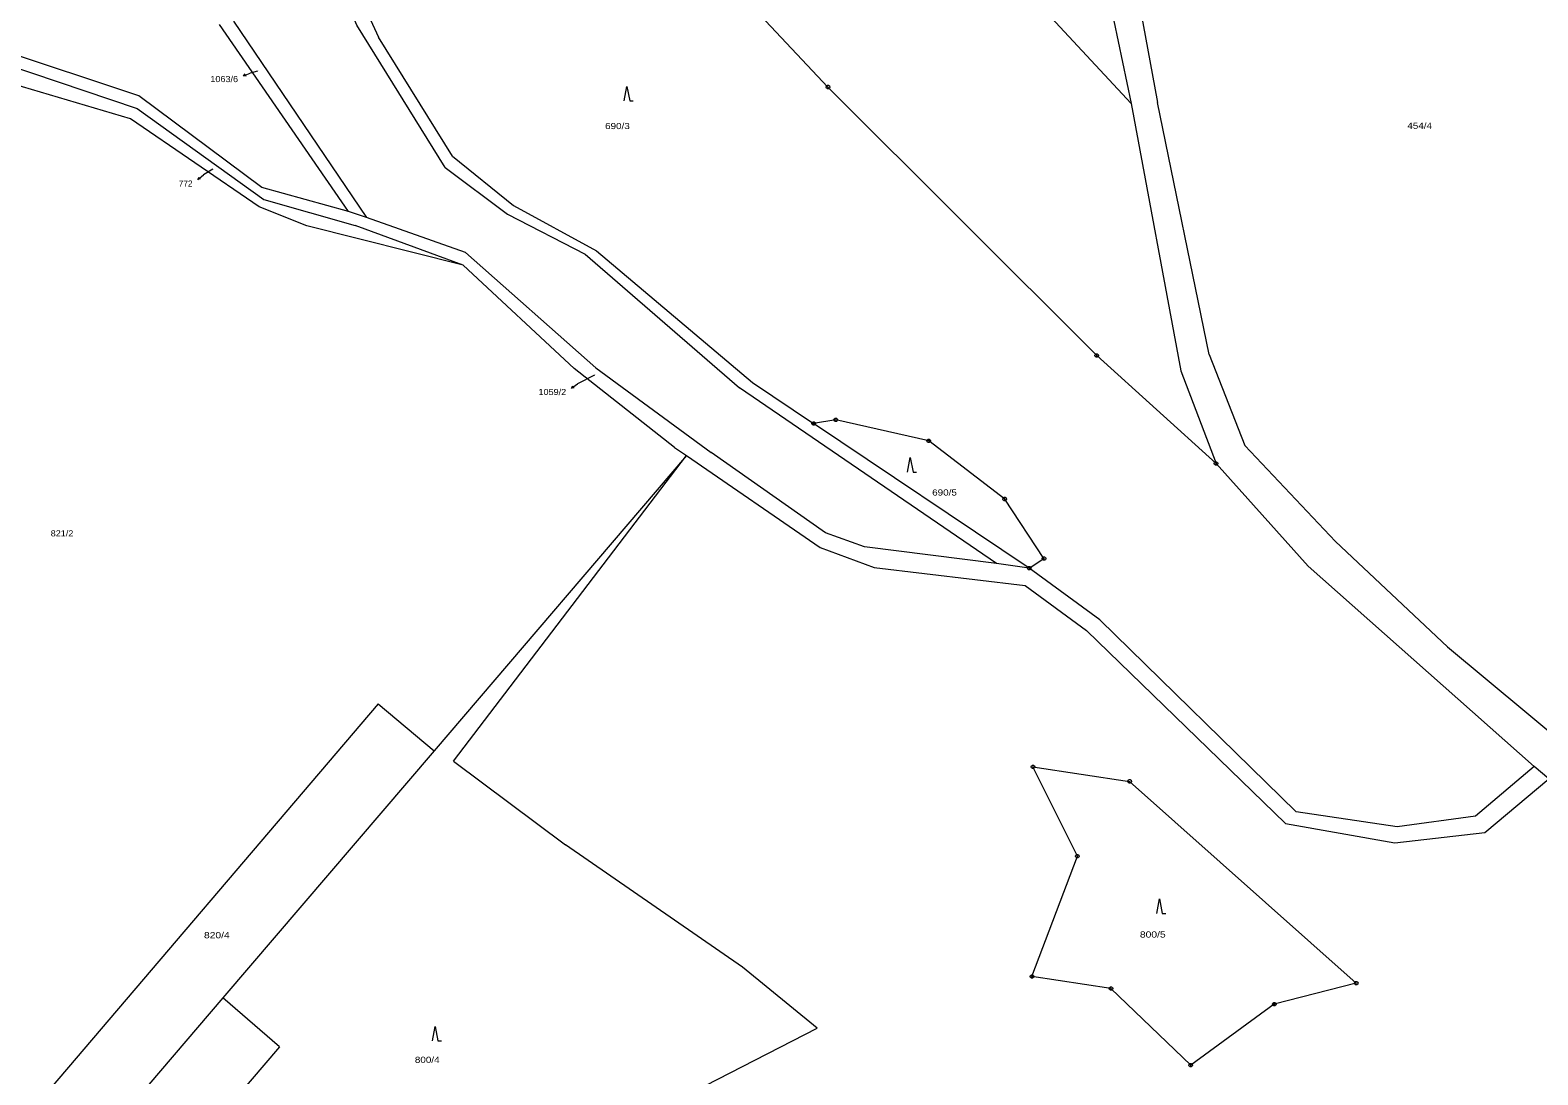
# Model space of a CAD drawing. Extents: x -687390 to -684106, y -954833 to -951648.
# Drawn here: x -686740.5 to -686324.4, y -954277 to -953988.7 of the extents above; entities that cross this region are included whole.
import ezdxf
from ezdxf.enums import TextEntityAlignment as Align

# ---------------------------------------------------------------- set-up
doc = ezdxf.new("R2010")
doc.units = 0
doc.header["$LTSCALE"] = 0.68
for name, color, linetype, lineweight in [('1', 7, 'Continuous', 13), ('3', 7, 'Continuous', 13), ('7', 7, 'Continuous', 13), ('8', 7, 'Continuous', 13)]:
    doc.layers.add(name, color=color, linetype=linetype, lineweight=lineweight)
doc.layers.add('2', color=7, linetype='Continuous')

msp = doc.modelspace()

# ---------------------------------------------------------------- linework, layer by layer
at = {"layer": '1'}
for p, q in [((-686435.8, -953973.36), (-686429.32, -954008.64)), ((-686684.36, -953986.27), (-686647.65, -954040.42)), ((-686710.48, -954006.85), (-686760.32, -953990.26)), ((-686652.64, -954038.79), (-686688.23, -953987.18)), ((-686623.91, -954023.47), (-686644.32, -953990.68)), ((-686415.07, -954078.25), (-686429.32, -954008.64)), ((-686675.98, -954035.41), (-686650.78, -954042.67)), ((-686620.99, -954053.54), (-686650.78, -954042.67)), ((-686620.33, -954050.04), (-686584.36, -954081.88)), ((-686587.31, -954050.52), (-686544.75, -954087.39)), ((-686620.99, -954053.54), (-686590.32, -954082.07)), ((-686562.61, -954103.89), (-686590.32, -954082.07)), ((-686584.36, -954081.88), (-686552.57, -954105.27)), ((-686541.12, -954085.95), (-686524.24, -954097.28)), ((-686473.74, -954135.88), (-686544.75, -954087.39)), ((-686464.75, -954137.19), (-686524.24, -954097.28)), ((-686559.35, -954106.13), (-686629, -954187.58)), ((-686623.68, -954190.45), (-686559.35, -954106.13)), ((-686521.01, -954127.47), (-686552.57, -954105.27)), ((-686464.75, -954137.19), (-686473.74, -954135.88)), ((-686445.22, -954151.42), (-686464.75, -954137.19)), ((-686391.04, -954204.4), (-686445.22, -954151.42)), ((-686644.44, -954174.63), (-686742.34, -954289.46)), ((-686644.44, -954174.63), (-686629, -954187.58)), ((-686629, -954187.58), (-686687.29, -954255.75)), ((-686623.68, -954190.45), (-686592.76, -954213.51)), ((-686543.89, -954247.28), (-686592.76, -954213.51)), ((-686671.65, -954269.27), (-686687.29, -954255.75))]:
    msp.add_line(p, q, dxfattribs=at)
for points in [[(-686413.2, -954108.29), (-686446.13, -954078.52), (-686520.3, -954004.42), (-686538.89, -953984.63), (-686584.5, -953936.92), (-686630.31, -953891.41), (-686671.47, -953851.65), (-686680.28, -953835.1), (-686694.74, -953810.32)], [(-686625.98, -954026.58), (-686650.34, -953987.3), (-686673.27, -953932.99), (-686680.76, -953921.95), (-686703.81, -953912.83), (-686715.91, -953900.78), (-686720.34, -953885.8), (-686724.86, -953861.07)], [(-686721.8, -953861.89), (-686719.33, -953876.68), (-686712.55, -953899.17), (-686702.88, -953909.09), (-686676.69, -953917.54), (-686670.12, -953929.75), (-686657.88, -953961.18), (-686644.32, -953990.68)], [(-686447.37, -953933.46), (-686441.4, -953986.17), (-686436.59, -954008.97), (-686491.9, -953949.46)], [(-686761.96, -953993.12), (-686710.98, -954010.32), (-686675.98, -954035.41)], [(-686620.99, -954053.54), (-686664.09, -954042.73), (-686677.24, -954037.48), (-686712.79, -954013.18), (-686767.53, -953997.01)], [(-686620.33, -954050.04), (-686647.65, -954040.42), (-686652.64, -954038.79), (-686676.5, -954032.1), (-686710.48, -954006.85)], [(-686436.59, -954008.97), (-686422.88, -954082.73), (-686413.2, -954108.29), (-686387.72, -954136.6), (-686325.35, -954191.87), (-686341.6, -954205.6)], [(-686623.91, -954023.47), (-686607.04, -954037.1), (-686584.2, -954049.58), (-686541.12, -954085.95)], [(-686625.98, -954026.58), (-686608.76, -954039.54), (-686587.31, -954050.52)], [(-686415.07, -954078.25), (-686405.25, -954103.32), (-686380.26, -954129.83), (-686349.27, -954158.9), (-686316.51, -954186.18), (-686309.24, -954181.25)], [(-686464.75, -954137.19), (-686460.67, -954134.56), (-686471.5, -954118.11), (-686492.47, -954102.06), (-686518.13, -954096.28), (-686524.24, -954097.28)], [(-686562.61, -954103.89), (-686559.35, -954106.13), (-686522.47, -954131.51)], [(-686473.74, -954135.88), (-686510.22, -954131.3), (-686521.01, -954127.47)], [(-686522.47, -954131.51), (-686507.54, -954136.97), (-686465.91, -954141.96)], [(-686465.91, -954141.96), (-686448.95, -954154.42), (-686394.03, -954207.61), (-686363.8, -954212.94), (-686338.97, -954210.15), (-686321.37, -954195.35), (-686325.35, -954191.87)], [(-686341.6, -954205.6), (-686363.18, -954208.52), (-686391.04, -954204.4)], [(-686580.46, -954315.03), (-686583.55, -954312.58), (-686602.14, -954304.61), (-686523.27, -954264.12), (-686543.89, -954247.28)], [(-686687.29, -954255.75), (-686728.73, -954304.2), (-686731.29, -954307.19)], [(-686671.65, -954269.27), (-686707.24, -954310.98), (-686692.71, -954315.68)]]:
    msp.add_lwpolyline(points, dxfattribs=at)
msp.add_lwpolyline([(-686374.51, -954251.74), (-686397.12, -954257.51), (-686420.19, -954274.35), (-686442.2, -954253.18), (-686464, -954249.86), (-686451.45, -954216.67), (-686463.71, -954192), (-686437.03, -954196.02)], close=True, dxfattribs=at)
at = {"layer": '3'}
for points in [[(-686576.51, -954008.26), (-686575.76, -954004.26), (-686575.01, -954008.26), (-686574.01, -954008.26)], [(-686498.32, -954110.67), (-686497.57, -954106.67), (-686496.82, -954110.67), (-686495.82, -954110.67)], [(-686429.55, -954232.46), (-686428.8, -954228.46), (-686428.05, -954232.46), (-686427.05, -954232.46)], [(-686629.42, -954267.64), (-686628.67, -954263.64), (-686627.92, -954267.64), (-686626.92, -954267.64)]]:
    msp.add_lwpolyline(points, dxfattribs=at)
at = {"layer": '7'}
for p, q in [((-686681.575, -954001.368), (-686679.73, -954000.57)), ((-686677.72, -954000.02), (-686679.73, -954000.57)), ((-686690.02, -954027.09), (-686692.62, -954028.66)), ((-686694.176, -954029.932), (-686692.62, -954028.66)), ((-686591.032, -954087.503), (-686589.4, -954086.33)), ((-686584.71, -954083.88), (-686589.4, -954086.33))]:
    msp.add_line(p, q, dxfattribs=at)
for points in [[(-686680.827, -954001.409), (-686681.575, -954001.368), (-686681.093, -954000.794)], [(-686693.446, -954029.767), (-686694.176, -954029.932), (-686693.87, -954029.249)], [(-686590.293, -954087.384), (-686591.032, -954087.503), (-686590.684, -954086.84)]]:
    msp.add_lwpolyline(points, dxfattribs=at)
at = {"layer": '8'}
for p, q in [((-686520.42, -954004.42), (-686520.18, -954004.42)), ((-686446.25, -954078.52), (-686446.01, -954078.52)), ((-686524.36, -954097.28), (-686524.12, -954097.28)), ((-686518.25, -954096.28), (-686518.01, -954096.28)), ((-686492.59, -954102.06), (-686492.35, -954102.06)), ((-686413.32, -954108.29), (-686413.08, -954108.29)), ((-686471.62, -954118.11), (-686471.38, -954118.11)), ((-686460.79, -954134.56), (-686460.55, -954134.56)), ((-686464.87, -954137.19), (-686464.63, -954137.19)), ((-686463.83, -954192), (-686463.59, -954192)), ((-686437.15, -954196.02), (-686436.91, -954196.02)), ((-686451.57, -954216.67), (-686451.33, -954216.67)), ((-686464.12, -954249.86), (-686463.88, -954249.86)), ((-686374.63, -954251.74), (-686374.39, -954251.74)), ((-686442.32, -954253.18), (-686442.08, -954253.18)), ((-686397.24, -954257.51), (-686397, -954257.51)), ((-686420.31, -954274.35), (-686420.07, -954274.35))]:
    msp.add_line(p, q, dxfattribs=at)
for points in [[(-686520.15, -954003.94), (-686519.9, -954004.12), (-686519.8, -954004.41), (-686519.9, -954004.7), (-686520.15, -954004.88), (-686520.46, -954004.88), (-686520.71, -954004.7), (-686520.81, -954004.41), (-686520.71, -954004.12), (-686520.46, -954003.94)], [(-686445.98, -954078.04), (-686445.73, -954078.22), (-686445.63, -954078.51), (-686445.73, -954078.8), (-686445.98, -954078.98), (-686446.29, -954078.98), (-686446.54, -954078.8), (-686446.64, -954078.51), (-686446.54, -954078.22), (-686446.29, -954078.04)], [(-686524.09, -954096.8), (-686523.84, -954096.98), (-686523.74, -954097.27), (-686523.84, -954097.56), (-686524.09, -954097.74), (-686524.4, -954097.74), (-686524.65, -954097.56), (-686524.75, -954097.27), (-686524.65, -954096.98), (-686524.4, -954096.8)], [(-686517.98, -954095.8), (-686517.73, -954095.98), (-686517.63, -954096.27), (-686517.73, -954096.56), (-686517.98, -954096.74), (-686518.29, -954096.74), (-686518.54, -954096.56), (-686518.64, -954096.27), (-686518.54, -954095.98), (-686518.29, -954095.8)], [(-686492.32, -954101.58), (-686492.07, -954101.76), (-686491.97, -954102.05), (-686492.07, -954102.34), (-686492.32, -954102.52), (-686492.63, -954102.52), (-686492.88, -954102.34), (-686492.98, -954102.05), (-686492.88, -954101.76), (-686492.63, -954101.58)], [(-686413.05, -954107.81), (-686412.8, -954107.99), (-686412.7, -954108.28), (-686412.8, -954108.57), (-686413.05, -954108.75), (-686413.36, -954108.75), (-686413.61, -954108.57), (-686413.71, -954108.28), (-686413.61, -954107.99), (-686413.36, -954107.81)], [(-686471.35, -954117.63), (-686471.1, -954117.81), (-686471, -954118.1), (-686471.1, -954118.39), (-686471.35, -954118.57), (-686471.66, -954118.57), (-686471.91, -954118.39), (-686472.01, -954118.1), (-686471.91, -954117.81), (-686471.66, -954117.63)], [(-686460.52, -954134.08), (-686460.27, -954134.26), (-686460.17, -954134.55), (-686460.27, -954134.84), (-686460.52, -954135.02), (-686460.83, -954135.02), (-686461.08, -954134.84), (-686461.18, -954134.55), (-686461.08, -954134.26), (-686460.83, -954134.08)], [(-686464.6, -954136.71), (-686464.35, -954136.89), (-686464.25, -954137.18), (-686464.35, -954137.47), (-686464.6, -954137.65), (-686464.91, -954137.65), (-686465.16, -954137.47), (-686465.26, -954137.18), (-686465.16, -954136.89), (-686464.91, -954136.71)], [(-686463.56, -954191.52), (-686463.31, -954191.7), (-686463.21, -954191.99), (-686463.31, -954192.28), (-686463.56, -954192.46), (-686463.87, -954192.46), (-686464.12, -954192.28), (-686464.22, -954191.99), (-686464.12, -954191.7), (-686463.87, -954191.52)], [(-686436.88, -954195.54), (-686436.63, -954195.72), (-686436.53, -954196.01), (-686436.63, -954196.3), (-686436.88, -954196.48), (-686437.19, -954196.48), (-686437.44, -954196.3), (-686437.54, -954196.01), (-686437.44, -954195.72), (-686437.19, -954195.54)], [(-686451.3, -954216.19), (-686451.05, -954216.37), (-686450.95, -954216.66), (-686451.05, -954216.95), (-686451.3, -954217.13), (-686451.61, -954217.13), (-686451.86, -954216.95), (-686451.96, -954216.66), (-686451.86, -954216.37), (-686451.61, -954216.19)], [(-686463.85, -954249.38), (-686463.6, -954249.56), (-686463.5, -954249.85), (-686463.6, -954250.14), (-686463.85, -954250.32), (-686464.16, -954250.32), (-686464.41, -954250.14), (-686464.51, -954249.85), (-686464.41, -954249.56), (-686464.16, -954249.38)], [(-686442.05, -954252.7), (-686441.8, -954252.88), (-686441.7, -954253.17), (-686441.8, -954253.46), (-686442.05, -954253.64), (-686442.36, -954253.64), (-686442.61, -954253.46), (-686442.71, -954253.17), (-686442.61, -954252.88), (-686442.36, -954252.7)], [(-686374.36, -954251.26), (-686374.11, -954251.44), (-686374.01, -954251.73), (-686374.11, -954252.02), (-686374.36, -954252.2), (-686374.67, -954252.2), (-686374.92, -954252.02), (-686375.02, -954251.73), (-686374.92, -954251.44), (-686374.67, -954251.26)], [(-686396.97, -954257.03), (-686396.72, -954257.21), (-686396.62, -954257.5), (-686396.72, -954257.79), (-686396.97, -954257.97), (-686397.28, -954257.97), (-686397.53, -954257.79), (-686397.63, -954257.5), (-686397.53, -954257.21), (-686397.28, -954257.03)], [(-686420.04, -954273.87), (-686419.79, -954274.05), (-686419.69, -954274.34), (-686419.79, -954274.63), (-686420.04, -954274.81), (-686420.35, -954274.81), (-686420.6, -954274.63), (-686420.7, -954274.34), (-686420.6, -954274.05), (-686420.35, -954273.87)]]:
    msp.add_lwpolyline(points, close=True, dxfattribs=at)

# ---------------------------------------------------------------- texts
at = {"layer": '2'}
for s, height, width, p in [('1063/6', 0.1, 1.1, (-686677.674, -954000.02)), ('690/3', 1.7, 1.2, (-686581.806, -954016.02)), ('454/4', 1.7, 1.2, (-686360.405, -954015.95)), ('1059/2', 0.1, 1.1, (-686584.664, -954083.88)), ('690/5', 1.7, 1.2, (-686491.536, -954117.15)), ('821/2', 1.7, 1.1, (-686734.805, -954128.42)), ('820/4', 1.7, 1.25, (-686692.505, -954239.31)), ('800/5', 1.7, 1.25, (-686434.205, -954239.12)), ('800/4', 1.7, 1.2, (-686634.305, -954273.7))]:
    msp.add_text(s, height=height, dxfattribs=dict(at, width=width)).set_placement(p)
msp.add_text('772', height=0.1, dxfattribs=at).set_placement((-686689.992, -954027.09))
at = {"layer": '7', "width": 1.1}
for s, p in [('1063/6', (-686683.096, -954003.06)), ('1059/2', (-686592.536, -954089.42))]:
    msp.add_text(s, height=1.7, dxfattribs=at).set_placement(p, align=Align.RIGHT)
at = {"layer": '7'}
msp.add_text('772', height=1.7, dxfattribs=at).set_placement((-686695.666, -954031.91), align=Align.RIGHT)

doc.saveas('drawing.dxf')
